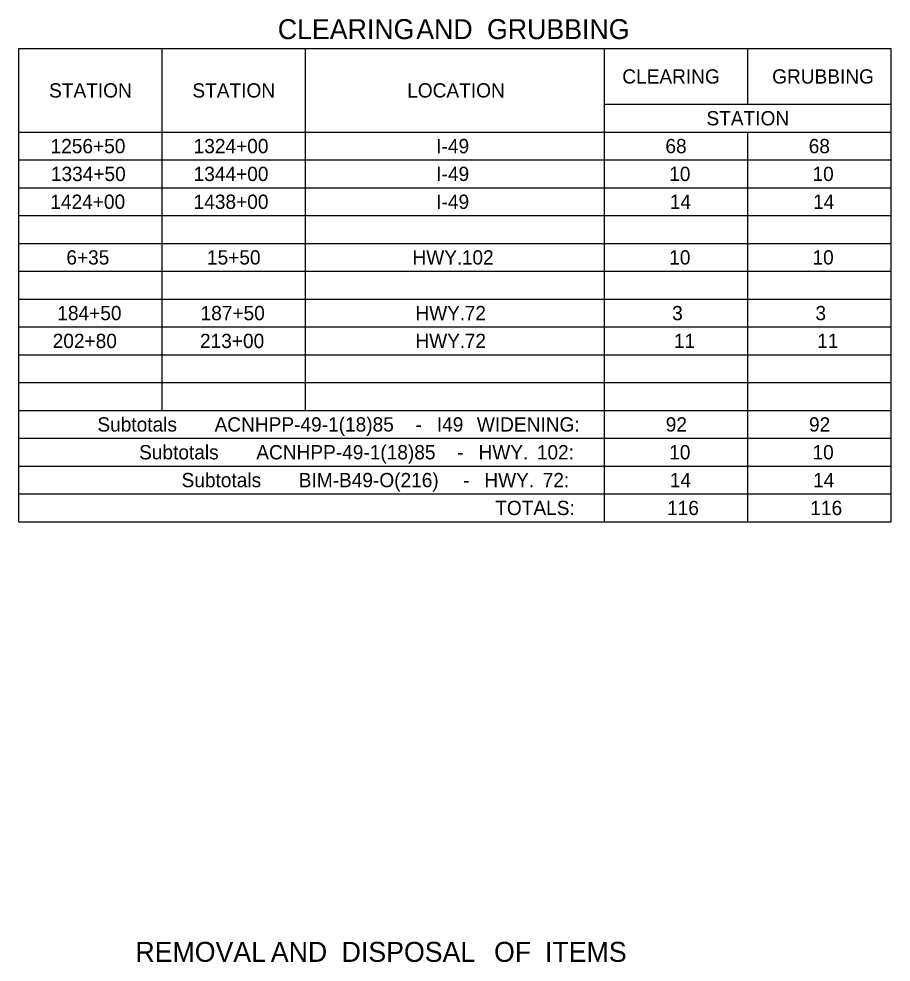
# Model space of a CAD drawing. Extents: x 1226657 to 1228145, y 151309 to 152305.
# Drawn here: x 1226911.8 to 1227217.4, y 151937.3 to 152267.8 of the extents above; entities that cross this region are included whole.
import ezdxf

# ---------------------------------------------------------------- set-up
doc = ezdxf.new("R2010")
doc.units = 0
doc.layers.add('R_Dimension', color=7, linetype='Continuous')

msp = doc.modelspace()

# ---------------------------------------------------------------- linework, layer by layer
at = {"layer": 'R_Dimension'}
for p, q in [((1226911.79, 152257.33), (1227217.45, 152257.33)), ((1226911.79, 152091.58), (1226911.79, 152257.33)), ((1226962, 152130.58), (1226962, 152257.33)), ((1227012.21, 152130.58), (1227012.21, 152257.33)), ((1227117.02, 152091.58), (1227117.02, 152257.33)), ((1227167.24, 152237.83), (1227167.24, 152257.33)), ((1227217.45, 152091.58), (1227217.45, 152257.33)), ((1227117.02, 152237.83), (1227217.45, 152237.83)), ((1226911.79, 152228.08), (1227217.45, 152228.08)), ((1227167.24, 152091.58), (1227167.24, 152228.08)), ((1226911.79, 152218.33), (1227217.45, 152218.33)), ((1226911.79, 152208.58), (1227217.45, 152208.58)), ((1226911.79, 152198.83), (1227217.45, 152198.83)), ((1226911.79, 152189.08), (1227217.45, 152189.08)), ((1226911.79, 152179.33), (1227217.45, 152179.33)), ((1226911.79, 152169.58), (1227217.45, 152169.58)), ((1226911.79, 152159.83), (1227217.45, 152159.83)), ((1226911.79, 152150.08), (1227217.45, 152150.08)), ((1226911.79, 152140.33), (1227217.45, 152140.33)), ((1226911.79, 152130.58), (1227217.45, 152130.58)), ((1226911.79, 152120.83), (1227217.45, 152120.83)), ((1226911.79, 152111.08), (1227217.45, 152111.08)), ((1226911.79, 152101.33), (1227217.45, 152101.33)), ((1226911.79, 152091.58), (1227217.45, 152091.58))]:
    msp.add_line(p, q, dxfattribs=at)

# ---------------------------------------------------------------- texts
for s, height, p in [('CLEARING', 7, (1227002.53, 152260.65)), (' AND', 7, (1227048.44, 152260.65)), (' GRUBBING', 7, (1227073.24, 152260.65)), ('CLEARING', 5, (1227123.23, 152245.08)), ('GRUBBING', 5, (1227175.75, 152245.08)), ('STATION', 5, (1226922.38, 152240.2)), ('STATION', 5, (1226972.6, 152240.2)), ('LOCATION', 5, (1227047.87, 152240.2)), ('STATION', 5, (1227152.73, 152230.45)), ('1256+50', 5, (1226922.9, 152220.7)), ('1324+00', 5, (1226973.03, 152220.7)), ('I-49', 5, (1227058.06, 152220.7)), ('68', 5, (1227138.35, 152220.7)), ('68', 5, (1227188.56, 152220.7)), ('1334+50', 5, (1226923.01, 152210.95)), ('1344+00', 5, (1226973.03, 152210.95)), ('I-49', 5, (1227058.06, 152210.95)), ('10', 5, (1227139.67, 152210.95)), ('10', 5, (1227189.88, 152210.95)), ('1424+00', 5, (1226922.82, 152201.2)), ('1438+00', 5, (1226973.03, 152201.2)), ('I-49', 5, (1227058.06, 152201.2)), ('14', 5, (1227139.89, 152201.2)), ('14', 5, (1227190.1, 152201.2)), ('6+35', 5, (1226928.43, 152181.7)), ('15+50', 5, (1226977.71, 152181.7)), ('HWY.', 5, (1227049.72, 152181.7)), (' 102', 5, (1227065.15, 152181.7)), ('10', 5, (1227139.67, 152181.7)), ('10', 5, (1227189.88, 152181.7)), ('184+50', 5, (1226925.26, 152162.2)), ('187+50', 5, (1226975.47, 152162.2)), ('HWY.', 5, (1227050.74, 152162.2)), (' 72', 5, (1227066.17, 152162.2)), ('3', 5, (1227140.71, 152162.2)), ('3', 5, (1227190.92, 152162.2)), ('202+80', 5, (1226923.64, 152152.45)), ('213+00', 5, (1226975.27, 152152.45)), ('HWY.', 5, (1227050.74, 152152.45)), (' 72', 5, (1227066.17, 152152.45)), ('11', 5, (1227141.3, 152152.45)), ('11', 5, (1227191.52, 152152.45)), ('Subtotals', 5, (1226939.31, 152123.2)), (' ACNHPP-49-1(18)85', 5, (1226978.52, 152123.2)), (' I49', 5, (1227056.4, 152123.2)), (' WIDENING:', 5, (1227070.41, 152123.2)), ('92', 5, (1227138.47, 152123.2)), ('92', 5, (1227188.68, 152123.2)), (' -', 5, (1227048.96, 152123.2)), ('Subtotals', 5, (1226953.92, 152113.45)), (' ACNHPP-49-1(18)85', 5, (1226993.13, 152113.45)), (' HWY.', 5, (1227071, 152113.45)), (' 102:', 5, (1227091.44, 152113.45)), ('10', 5, (1227139.67, 152113.45)), ('10', 5, (1227189.88, 152113.45)), (' -', 5, (1227063.56, 152113.45)), ('Subtotals', 5, (1226968.8, 152103.7)), (' BIM-B49-O(216)', 5, (1227008.01, 152103.7)), (' HWY.', 5, (1227073.05, 152103.7)), (' 72:', 5, (1227093.48, 152103.7)), ('14', 5, (1227139.89, 152103.7)), ('14', 5, (1227190.1, 152103.7)), (' -', 5, (1227065.61, 152103.7)), ('TOTALS:', 5, (1227078.72, 152093.95)), ('116', 5, (1227138.92, 152093.95)), ('116', 5, (1227189.13, 152093.95)), ('REMOVAL', 7, (1226952.62, 151937.45)), (' AND', 7, (1226997.48, 151937.45)), (' DISPOSAL', 7, (1227022.29, 151937.45)), (' OF', 7, (1227075.7, 151937.45)), (' ITEMS', 7, (1227093.55, 151937.45))]:
    msp.add_text(s, height=height, dxfattribs=at).set_placement(p)

doc.saveas('drawing.dxf')
